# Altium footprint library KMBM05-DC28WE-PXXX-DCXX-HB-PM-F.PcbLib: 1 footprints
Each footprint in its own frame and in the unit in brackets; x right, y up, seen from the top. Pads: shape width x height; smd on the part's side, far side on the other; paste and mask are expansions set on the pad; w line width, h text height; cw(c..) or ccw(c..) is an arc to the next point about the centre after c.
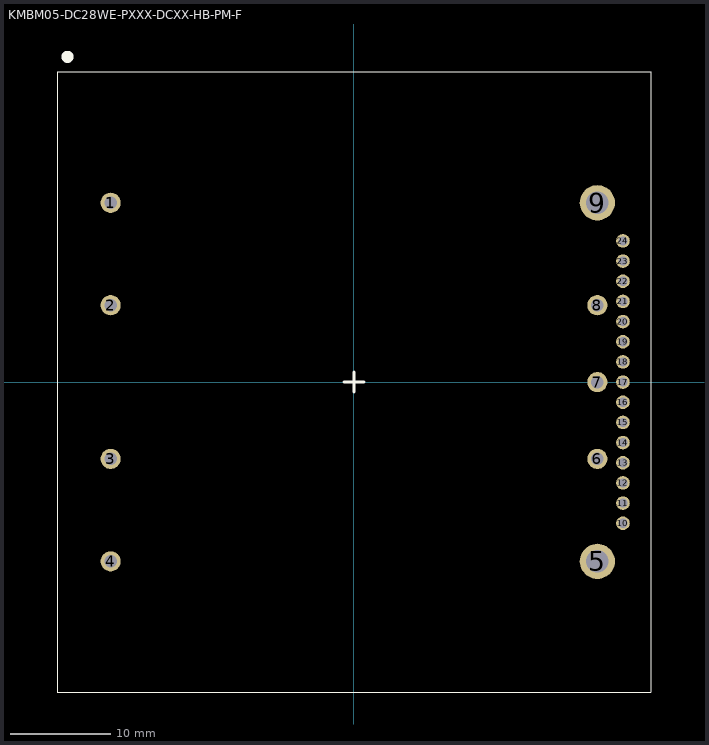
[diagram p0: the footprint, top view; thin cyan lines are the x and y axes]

## KMBM05-DC28WE-PXXX-DCXX-HB-PM-F [mm] "KMBM05-DC28WE-PXXX-DCXX-HB-PM-F"
height 13
pads (24):
  round 2 hole 1.25: 1(-24.13,17.78) 2(-24.13,7.62) 3(-24.13,-7.62) 4(-24.13,-17.78) 6(24.13,-7.62) 7(24.13,0) 8(24.13,7.62)
  round 3.5 hole 2.25: 5(24.13,-17.78) 9(24.13,17.78)
  round 1.35 hole 0.9: 10(26.67,-14) 11(26.67,-12) 12(26.67,-10) 13(26.67,-8) 14(26.67,-6) 15(26.67,-4) 16(26.67,-2) 17(26.67,0) 18(26.67,2) 19(26.67,4) 20(26.67,6) 21(26.67,8) 22(26.67,10) 23(26.67,12) 24(26.67,14)
Top Overlay:
  circle w1: c-28.4,32.253 r0.1
  lines w0.1: -29.45,-30.75 29.45,-30.75 29.45,30.75 -29.45,30.75 -29.45,-30.75
  lines w0.3: -1,0 0,0 ; 0,-1 0,0 ; 0,1 0,0 ; 1,0 0,0
Bottom Overlay:
  circle w1: c-28.4,29.243 r0.1
  text "CASE" at -28.1,-6.337 h0.7
  text "-VIN" at -28.1,-16.555 h0.7
  text "ON/OFF" at -28.1,9.603 h0.7
  text "+VIN" at -28.1,19.005 h0.7
  text "+VOUT" at 28.8,19.413 h0.7
  text "+SENSE" at 28.8,9.603 h0.7
  text "TRIM" at 28.8,1.228 h0.7
  text "-SENSE" at 28.8,-5.637 h0.7
  text "-VOUT" at 28.8,-16.147 h0.7
3D body "KMBM05-PM-F.STEP": height 13.01, standoff -7.36, extent -29.2,-40 29.2,40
